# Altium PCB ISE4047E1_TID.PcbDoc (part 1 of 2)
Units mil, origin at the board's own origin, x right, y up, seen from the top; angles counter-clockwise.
Board outline 2952.76 x 1377.95 mil, 4 copper layers (Layer 1 - Top Layer, Layer 2 - GND, Layer 3 - PWR, Layer 4 - Bottom Layer), stack 43.668 mil thick; 130 components, 47 nets, 287 pads, 266 vias.
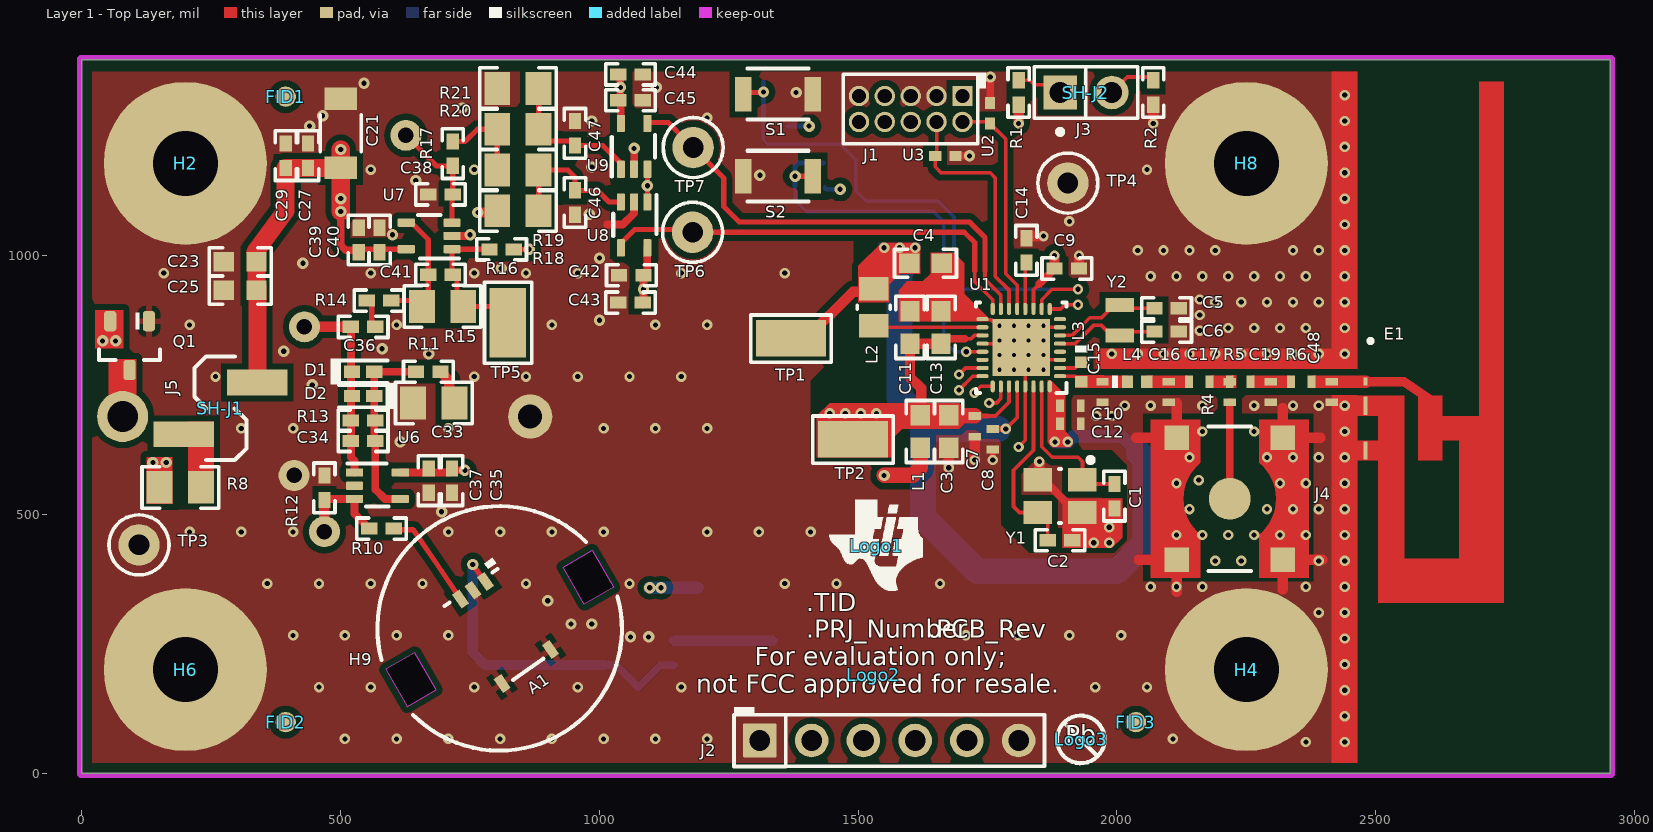
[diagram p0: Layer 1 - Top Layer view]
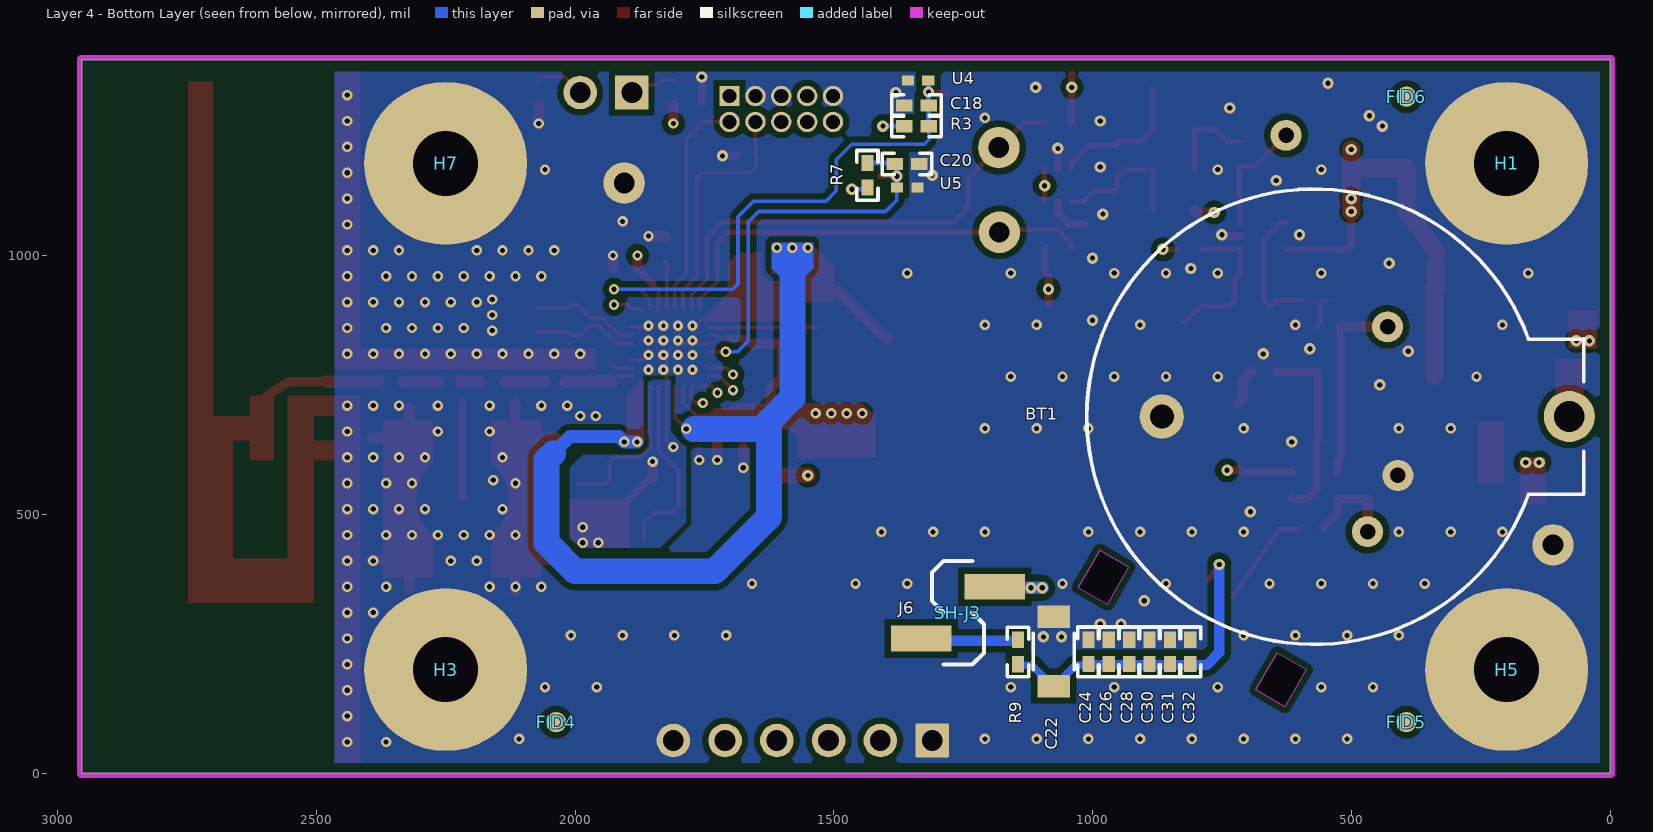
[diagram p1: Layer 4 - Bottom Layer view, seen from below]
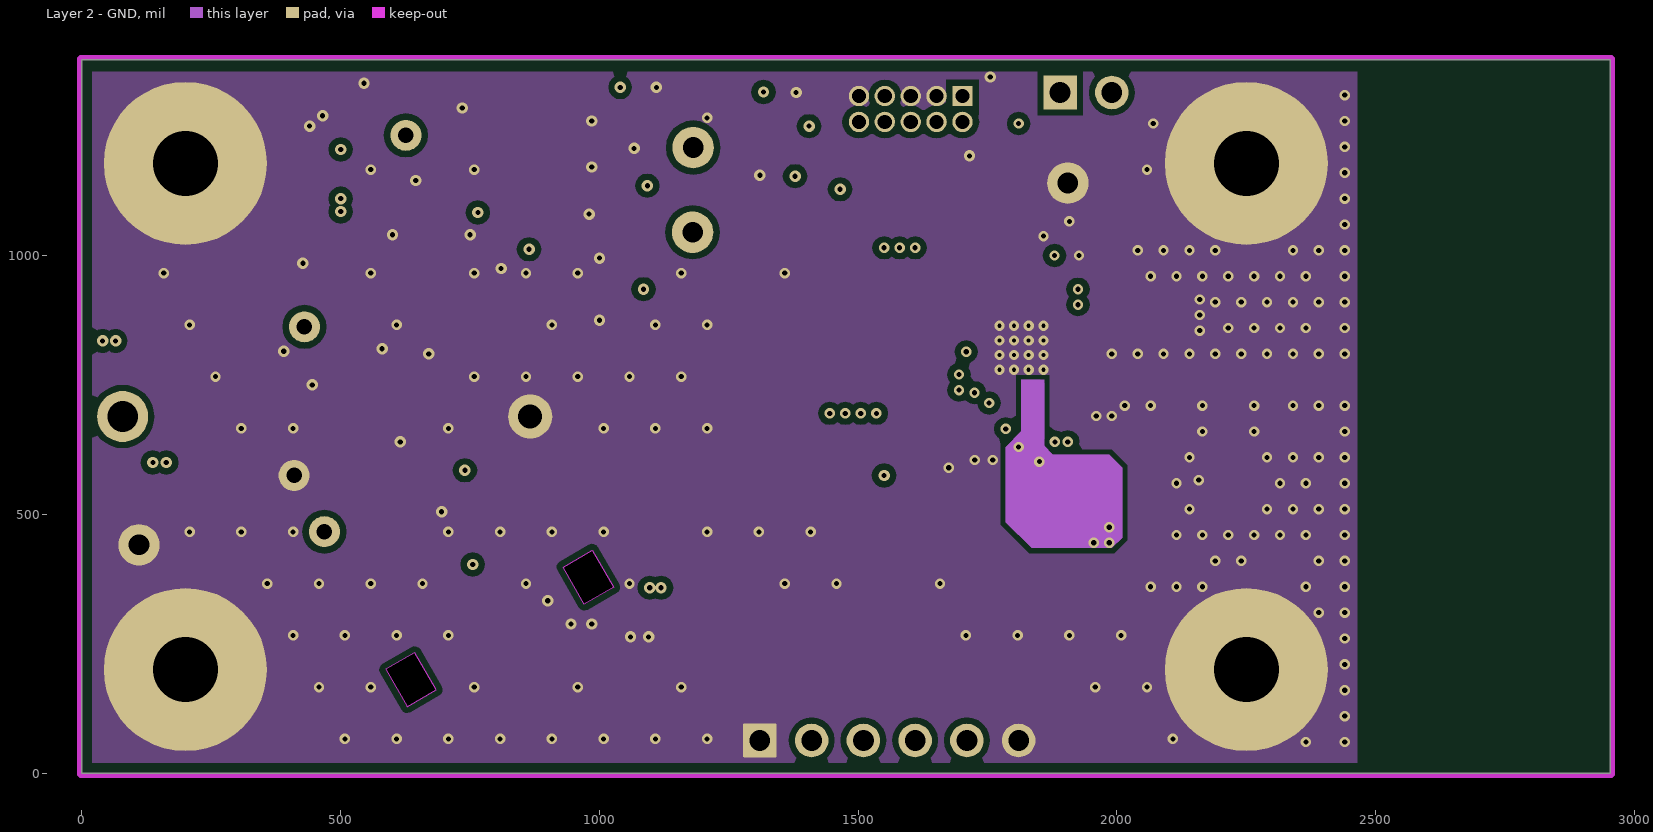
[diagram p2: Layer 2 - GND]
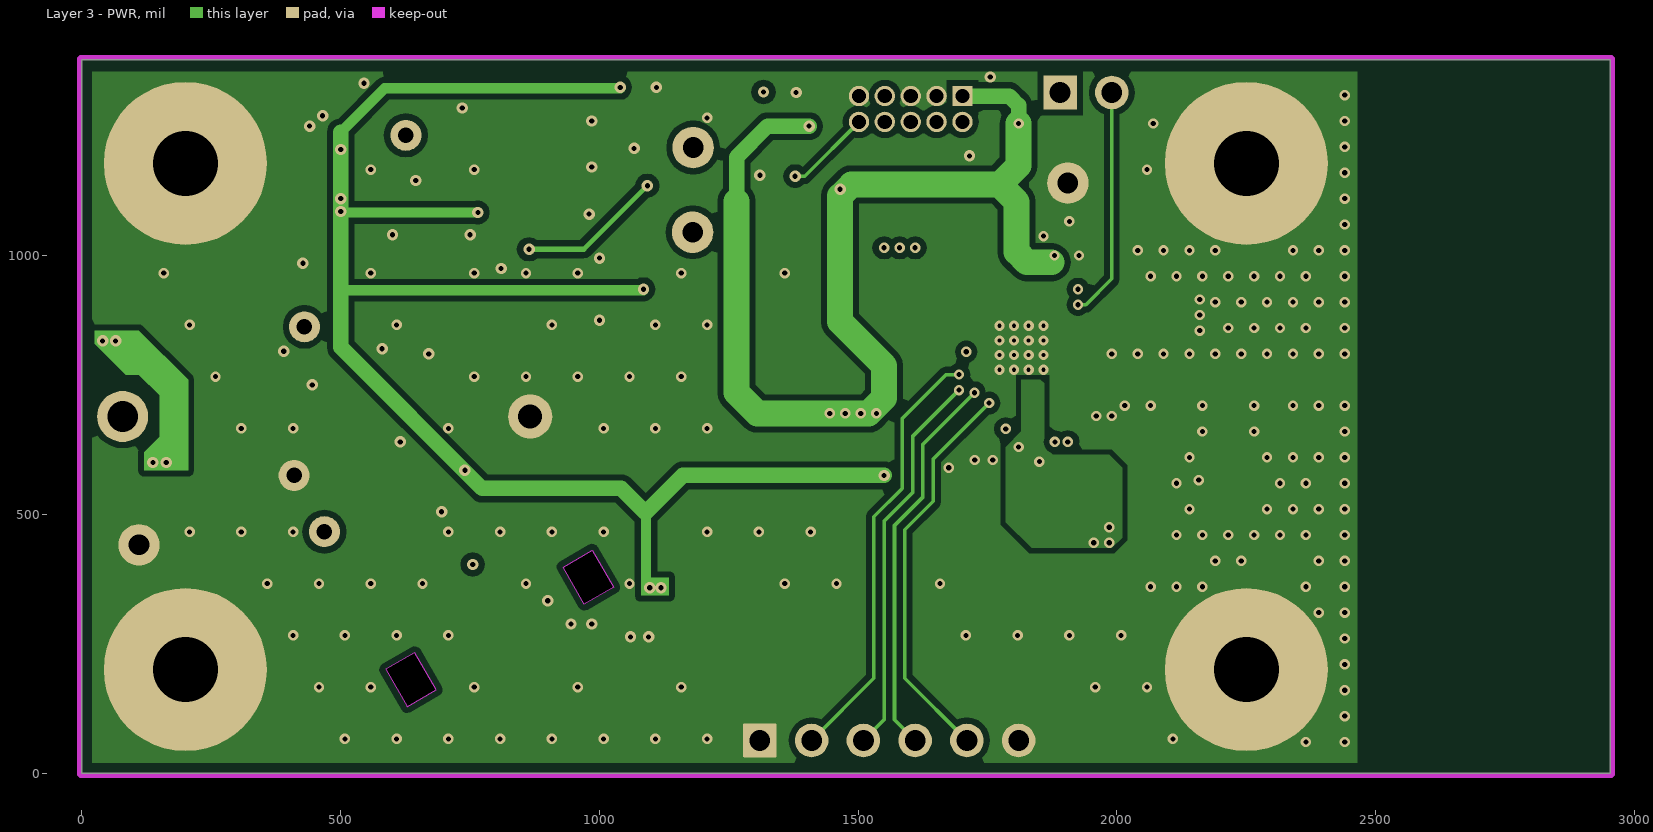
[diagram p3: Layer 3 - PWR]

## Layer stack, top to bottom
Top Solder: solder mask 0.4, Solder Resist, Dk 3.5
Layer 1 - Top Layer: signal copper 1.417
Dielectric 1: prepreg 14, 370HR, Dk 4.2
Layer 2 - GND: signal copper 1.417
Dielectric 2: core 10, 370HR, Dk 4.2
Layer 3 - PWR: signal copper 1.417
Dielectric 3: prepreg 14, 370HR, Dk 4.2
Layer 4 - Bottom Layer: signal copper 1.417
Bottom Solder: solder mask 0.4, Solder Resist, Dk 3.5

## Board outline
0,0 2952.76,0 2952.76,1377.95 0,1377.95

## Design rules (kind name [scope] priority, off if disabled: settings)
Clearance Clearance_1 [inpoly] p1: gap=12
Clearance "Stitching GND" [IsStitchingVia and InNet('GND') vs (IsVia and (Not IsStitchingVia)) Or IsPad] p2: gap=20
Clearance [All] p3: gap=6
ComponentClearance "ComponentClearance_RF Chain" [(InComponent('R4') OR InComponent('R5'))] p1: gap=0 collisioncheckmode=3 verticalgap=0 showdistances=FALSE
ComponentClearance ComponentClearance_Shunt [InComponentClass('Header') vs InComponentClass('Shunt')] p2: gap=0 collisioncheckmode=3 verticalgap=0 showdistances=FALSE
ComponentClearance ComponentClearance_H9 [incomponent('A1') vs incomponent('H9')] p3: gap=0 collisioncheckmode=3 verticalgap=0 showdistances=FALSE
ComponentClearance [All] p4: gap=3.94 collisioncheckmode=3 verticalgap=3.94 showdistances=FALSE
FabricationTestPointUsage TestPointUsage [All] p1: valid=0 allowmultiple=FALSE
FabricationTestpoint Testpoint [All] p1: side=3 testpointundercomponent=TRUE minsize=40 maxsize=100 preferedsize=60 minholesize=0 maxholesize=40 preferedholesize=32 testpointgrid=1 allowsidetop=TRUE allowsidebottom=TRUE usegrid=TRUE gridtolerance=0.01
HoleSize [All] p1: absolutevalues=TRUE maxlimit=500 minlimit=7.8 maxpercent=80.000 minpercent=20.000
MinimumSolderMaskSliver [All] p1: minsoldermaskwidth=4
PolygonConnect PolygonConnect_TR [incomponent('A1') or  incomponent('Q1') or incomponent('J4')] p1: connectstyle=Relief reliefconductorwidth=12 reliefentries=4 polygonreliefangle="90 Angle" airgapwidth=10
PolygonConnect [All] p2: connectstyle=Direct reliefconductorwidth=10 reliefentries=4 polygonreliefangle="90 Angle" airgapwidth=10
RoutingVias [All] p1: holewidth=10 width=22 viastyle="Through Hole" minholewidth=7.8 minwidth=19 maxholewidth=28 maxwidth=50
SilkToBoardRegionClearance [All] p1 off:
SilkToSilkClearance SilkToSilkClearance_1 [(HasFootprint('Pb-Free_Overlay_Medium') OR HasFootprint('Pb-Free_Overlay_Small')) vs (HasFootprint('Pb-Free_Overlay_Medium') OR HasFootprint('Pb-Free_Overlay_Small'))] p1: silktosilkclearance=0
SilkToSilkClearance [All] p2: silktosilkclearance=3
SilkToSolderMaskClearance SilkscreenOverComponentPads [IsPad] p1: minsilkscreentomaskgap=3 clearancetoexposedcopper=TRUE
SolderMaskExpansion [All] p1: expansion=1.97
UnpouredPolygon [All] p1: allowunpoured=FALSE
Width [All] p1: maxlimit=100 minlimit=6 preferedwidth=10 minimp=50.000000 maximp=50.000000 favimp=50.000000
21 further rules are at their usual default settings.

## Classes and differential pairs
component class FiducialMark: FID1 FID2 FID3 FID4 FID5 FID6
component class ISE4047E1_TID_Hardware: FID1 FID2 FID3 FID4 FID5 FID6 H1 H2 H3 H4 H5 H6 H7 H8 H9 Logo1 Logo2 Logo3 SH-J1 SH-J2 SH-J3 ZZ1 ZZ2 ZZ3 ZZ4
component class Logo: Logo1
component class "Mounting Holes": H2 H4 H6 H8
component class Header: J1 J2 J3 J5 J6
component class AssemblyNote: ZZ1 ZZ2 ZZ3 ZZ4
component class Shunt: SH-J1 SH-J2 SH-J3
component class ISE4047E1_MCU: C1 C2 C3 C4 C5 C6 C7 C8 C9 C10 C11 C12 C13 C14 C15 C16 C17 C18 C19 C20 C48 E1 J1 J2 J3 J4 L1 L2 L3 L4 R1 R2 R3 R4 R5 R6 R7 S1 S2 TP1 TP2 U1 U2 U3 U4 U5 Y1 Y2
component class ISE4047E1_POWER_PIR: A1 BT1 C21 C22 C23 C24 C25 C26 C27 C28 C29 C30 C31 C32 C33 C34 C35 C36 C37 C38 C39 C40 C41 C42 C43 C44 C45 C46 C47 D1 D2 J5 J6 Q1 R8 R9 R10 R11 R12 R13 R14 R15 R16 R17 R18 R19 R20 R21 TP3 TP4 TP5 TP6 TP7 U6 U7 U8 U9

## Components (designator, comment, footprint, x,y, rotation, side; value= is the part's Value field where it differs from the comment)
A1 "IRS-B210ST01-R1" Murata_IRS-B210ST01 807.09,279.53 r305 top locked
BT1 "BS-7" BAT_BS-7 472.44,688.98 r0 bottom locked
C1 "GRM1555C1E120JA01D" 0402 1995,535 r90 top
C2 "GRM1555C1E120JA01D" 0402 1890,450 r180 top
C3 "Used in BOM report" 0603 1675,660 r270 top
C4 "GRM188R60J106ME47D" 0603 1630,985 r180 top
C5 "GRM1555C1E120JA01D" 0402 2096,898 r0 top
C6 "GRM1555C1E120JA01D" 0402 2096,853 r0 top
C7 "GRM155R70J104KA01D" 0402S 1725,670 r270 top
C8 "GRM155R70J104KA01D" 0402S 1760,645 r270 top
C9 "GRM155R70J104KA01D" 0402 1903,975 r0 top
C10 "GRM155R70J104KA01D" 0402S 1910,710 r0 top
C11 "GRM188R60J106ME47D" 0603 1600,861 r270 top
C12 "Used in BOM report" 0402S 1910,675 r0 top
C13 "GRM188R71E104KA01D" 0603 1660,861 r270 top
C14 "GRM155R61A105KE15D" 0402 1825,1010 r90 top
C15 "GRM1555C1H1R2BA01D" 0402S 1972,736.3 r270 top
C16 "GRM1555C1H1R2BA01D" 0402S 2100,736.3 r270 top
C17 "GRM1555C1H120JA01D" 0402S 2159,756.3 r180 top
C18 "C1005X7R1H222K" 0402 1340,1290 r180 bottom
C19 "Used in BOM report" 0402S 2297,736.3 r90 top
C20 "C1005X7R1H222K" 0402 1358.37,1176.9 r0 bottom
C21 "C3216X5R1A107M160AC" 1206_190 500,1236.22 r90 top
C22 "C3216X5R1A107M160AC" 1206_190 1075,235 r90 bottom
C23 "C1608X5R0J106M" 0603 305.78,988.19 r180 top
C24 "GRM155R60J106ME44D" 0402 1007.89,234.25 r90 bottom
C25 "C1608X7R1C105K" 0603 305.78,933.07 r180 top
C26 "C1005X5R1A105K050BB" 0402 968.52,234.25 r90 bottom
C27 "C1005X7R1H104K050BB" 0402 437.01,1192.91 r90 top
C28 "C1005X7R1H104K050BB" 0402 929.15,234.25 r90 bottom
C29 "C1005X7R1C103K050BA" 0402 393.7,1192.91 r90 top
C30 "C1005X7R1C103K050BA" 0402 889.78,234.25 r90 bottom
C31 "C1005X7R1H102K" 0402 850.41,234.25 r90 bottom
C32 "C0402C101J3GACTU" 0402 811.04,234.25 r90 bottom
C33 "C2012X5R1A336M125AC" 0805_HV 680,715 r180 top
C34 "C1005X7R1E103K" 0402 543.31,641.73 r0 top
C35 "C1005X7R1H104K" 0402 715,565 r90 top
C36 "C1005X5R1A335K050BC" 0402 543.31,862.2 r180 top
C37 "C1005X7R1H102K" 0402 670,565 r270 top
C38 "C1005X7R1H104K" 0402 692.91,1118.11 r180 top
C39 "C1005X7R1H104K" 0402 535,1030 r270 top
C40 "C1005X7R1H102K" 0402 575,1030 r90 top
C41 "C1005C0G1E102J" 0402 693,963 r180 top
C42 "C1005X7R1H104K" 0402 1061.54,962.03 r0 top
C43 "C1005X7R1H102K" 0402 1060,909 r180 top
C44 "C1005X7R1H104K" 0402 1060,1350 r180 top
C45 "C1005X7R1H102K" 0402 1060,1300 r0 top
C46 "C1005X7R1H104K" 0402 952.76,1102.36 r270 top
C47 "C1005X7R1H104K" 0402 952.76,1236.22 r90 top
C48 "Used in BOM report" 0402S 2415,736.3 r90 top
D1 "1N4148X-TP" SOD-523 543.31,775.59 r0 top
D2 "1N4148X-TP" SOD-523 543.31,728.35 r180 top
E1 "ANTENNA_DN007A" ANTENNA_DN007A 2480.32,756.03 r270 top locked net-tie
FID1 "Fiducial" Fiducial10-20 393.7,1307.09 r0 top
FID2 "Fiducial" Fiducial10-20 393.7,98.42 r0 top
FID3 "Fiducial" Fiducial10-20 2036.61,98.42 r0 top
FID4 "Fiducial" Fiducial10-20 2036.61,98.42 r90 bottom
FID5 "Fiducial" Fiducial10-20 393.7,98.42 r90 bottom
FID6 "Fiducial" Fiducial10-20 393.7,1307.09 r90 bottom
H1 "1902C" Keystone_1902C#1 200,1177.95 r180 bottom
H2 "NY PMS 440 0025 PH" "NY PMS 440 0025 PH" 200,1177.95 r0 top
H3 "1902C" Keystone_1902C#2 2250,200 r180 bottom locked
H4 "NY PMS 440 0025 PH" "NY PMS 440 0025 PH" 2250,200 r0 top locked
H5 "1902C" Keystone_1902C#2 200,200 r180 bottom locked
H6 "NY PMS 440 0025 PH" "NY PMS 440 0025 PH" 200,200 r0 top locked
H7 "1902C" Keystone_1902C#1 2250,1177.95 r180 bottom
H8 "NY PMS 440 0025 PH" "NY PMS 440 0025 PH" 2250,1177.95 r0 top
H9 "IML-0669" Murata_IML-0669 807.09,279.53 r210 top locked
J1 "GRPB052VWVN-RC" CONN_GRPB052VWVN-RC 1601.42,1283.19 r180 top
J2 "TSW-106-07-G-S" TSW-106-07-G-S 1560,62.99 r0 top
J3 "TSW-102-07-G-S" TSW-102-07-G-S 1940,1315 r0 top
J4 "CONSMA001-SMD-G" Linx_CONSMA001-SMD-G 2218,530 r0 top
J5 "87898-0204" Molex_87898-0204 267.72,704.72 r90 top
J6 "87898-0204" Molex_87898-0204 1260,310 r90 bottom
L1 "BLM18HE152SN1D" 0603 1620,660 r90 top
L2 "CKS2125100M-T" 0805_145 1530,900 r90 top
L3 "LQG15HS15NJ02D" IND_LQG15H#1 1931,775 r270 top
L4 "LQG15HS2N0S02D" IND_LQG15H#2 2039,756.3 r0 top
Logo1 "Texas Instruments" TI_Symbol_Overlay_Small 1534.51,439.64 r0 top
Logo2 "FCC disclaimer" FCC_disclaimer_stacked 1529.51,189.64 r0 top
Logo3 "Pb-Free Symbol" Pb-Free_Overlay_Small 1930,65 r0 top
Q1 "SI2323DS" SOT-23 92,826 r270 top
R1 "CRCW04020000Z0ED" 0402 1810,1315 r270 top
R2 "CRCW0402100KFKED" 0402 2070,1315 r90 top
R3 "CRCW040247K5FKED" 0402 1340,1250 r0 bottom
R4 "CRCW04020000Z0ED" 0402S 2218,736.3 r270 top
R5 "CRCW04020000Z0ED" 0402S 2238,756.3 r0 top
R6 "CRCW04020000Z0ED" 0402S 2356,756.3 r0 top
R7 "CRCW040247K5FKED" 0402 1435,1155 r270 bottom
R8 "CRCW08050000Z0EA" 0805_HV 190,552 r0 top
R9 "CRCW0402619KFKED" 0402 1144,234 r90 bottom
R10 "CRCW04020000Z0ED" 0402 578.74,472.44 r180 top
R11 "CRCW04026K81FKED" 0402 669.29,775.59 r180 top
R12 "CRCW04021M30FKED" 0402 468.5,551.18 r270 top
R13 "CRCW04021M50FKED" 0402 543.31,681.1 r180 top
R14 "CRCW040268K1FKED" 0402 574,913 r0 top
R15 "RMCF0805JT15M0" 0805_HV 696.85,901.57 r0 top
R16 "CRCW04020000Z0ED" 0402 811.02,1011.81 r0 top
R17 "CRCW04020000Z0ED" 0402 716.54,1196.85 r90 top
R18 "RMCF0805JT15M0" 0805_HV 842.52,1086.61 r180 top
R19 "RMCF0805JT15M0" 0805_HV 842.52,1165.35 r0 top
R20 "RMCF0805JT15M0" 0805_HV 842.52,1244.09 r180 top
R21 "RMCF0805JT15M0" 0805_HV 842.52,1322.84 r0 top
S1 "B3U-1000P" SW_B3U-1000P 1345,1312 r180 top
S2 "B3U-1000P" SW_B3U-1000P 1345,1153.26 r0 top
SH-J1 "969102-0000-DA" SNT-100-BK-G#1 267.72,704.72 r270 top
SH-J2 "969102-0000-DA" SNT-100-BK-G#1 1940,1315 r0 top
SH-J3 "969102-0000-DA" SNT-100-BK-G#2 1260,310 r270 bottom
TP1 "5015" Testpoint_Keystone_Miniature 1370,840 r0 top
TP2 "5015" Testpoint_Keystone_Miniature 1490,645 r0 top
TP3 "5001" Keystone5001 110.24,440.94 r0 top
TP4 "5001" Keystone5001 1905,1140 r0 top
TP5 "5015" Testpoint_Keystone_Miniature 822.84,870.08 r90 top
TP6 "5004" Keystone5004 1180,1045 r0 top
TP7 "5004" Keystone5004 1181.1,1208.66 r0 top
U1 "CC2650F128RSMR" RSM0032B 1815,822 r180 top locked
U2 "TPD1E10B06DPYR" DPY0002A 1754.69,1275.04 r90 top
U3 "TPD1E10B06DPYR" DPY0002A 1668.35,1192.64 r0 top
U4 "TPD1E10B06DPYR" DPY0002A 1337,1338 r0 bottom
U5 "TPD1E10B06DPYR" DPY0002A 1358.09,1131.3 r180 bottom
U6 "LPV521MG" DCK0005A_N 570.87,555.12 r0 top
U7 "LPV521MG" DCK0005A_N 670.9,1037.87 r180 top
U8 "TLV3691IDCKR" DCK0005A_N 1066.93,1059.05 r270 top
U9 "TLV3691IDCKR" DCK0005A_N 1067,1211 r90 top
Y1 "TSX-3225 24.0000MF20G-AC3" EPSON_TSX-3225 1890,535 r270 top
Y2 "FC-12M 32.7680KA-A3" Epson_FC-12M 2005,875 r90 top
ZZ1 "These assemblies are ESD sensitive, ESD precautions shall be observed." AssemblyNote 160,1950 r0 top
ZZ2 "These assemblies must be clean and free from flux and all contaminants. Use of no clean flux is not acceptable." AssemblyNote 160,1820 r0 top
ZZ3 "These assemblies must comply with workmanship standards IPC-A-610 Class 2, unless otherwise specified." AssemblyNote 160,1695 r0 top
ZZ4 "After verifying lens of A1 is clean and undistorted, snap cover H9 over sensor A1 during final hardware assembly." AssemblyNote 160,1575 r0 top

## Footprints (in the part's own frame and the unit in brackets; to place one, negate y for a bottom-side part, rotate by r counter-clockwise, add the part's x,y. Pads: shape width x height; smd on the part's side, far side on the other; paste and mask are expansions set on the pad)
0402 [mm] "0402 from SM-752 data"
  rect 0.8x0.6 smd: 1(-0.6,0) 2(0.6,0)
  silkscreen extent -1.22,-0.52 1.22,0.52, body extent -0.55,-0.3 0.55,0.3, height 0.6
0402S [mil] "Based on C0402S footprint from PADS legacy"
  rect 15x24 smd: 1(-20,0) 2(20,0)
  body extent -22,-12 22,12, height 24
0603 [mm] "0603 from SM-752 data"
  rect 1x0.95 smd: 1(-0.8,0) 2(0.8,0)
  silkscreen extent -1.52,-0.69 1.52,0.69, body extent -0.87,-0.47 0.87,0.47, height 1
0805_145 [mm] "0805 / 1.45mm height"
  rect 1.15x1.45 smd: 1(-0.9,0) 2(0.9,0)
  silkscreen extent -0.1,-0.8 0.1,0.8, body extent -1.1,-0.72 1.1,0.72, height 1.45
0805_HV [mil] "0805 with 30mil clearance between pads"
  rect 50x63 smd: 1(-40,0) 2(40,0)
  silkscreen extent -74,-40 74,40, body extent -43,-29 43,29, height 57
1206_190 [mm] "1206_190"
  rect 1.1x1.6 smd: 1(-1.7,0) 2(1.7,0)
  silkscreen extent -0.9,-1 0.9,1, body extent -1.75,-0.95 1.75,0.95, height 1.9
ANTENNA_DN007A [mm] "SMD, 3-Leads"
  rect 0.4x0.2 smd paste-2 mask-2: 1(-0.007,0)
  rect 0.9x0.2 smd paste-2 mask-2: 2(1.18,-0.01) 3(3.37,0)
  Layer 1 - Top Layer region: 10.84,0.63 10.84,6.775 -14.715,6.775 -14.715,5.59 1.685,5.59 1.685,3.765 0.685,3.765 0.685,3.271 -0.225,1.951 -0.225,-0.11 0.21,-0.11 0.21,1.816 0.737,2.58 3.86,2.58 3.86,3.765 2.86,3.765 2.86,4.59 8.685,4.59 8.685,1.895 0.685,1.895 0.685,-0.11 1.66,-0.11 1.66,0.63 2.885,0.63 2.885,-0.11 3.86,-0.11 3.86,0.63
  silkscreen extent -2.11,0.15 -1.91,0.35
AssemblyNote [mil] "Assembly Note"
BAT_BS-7 [mm] "Memory Protection Devices CR2032 battery holder"
  round 2.5 hole 1.5: 1(-10,0)
  round 2.17 hole 1.181: 2(10,0)
  silkscreen extent -10.7,-11.16 13.68,11.18, body extent -10.69,-11.16 13.7,11.16, height 9.02
CONN_GRPB052VWVN-RC [mm] "SULLINS"
  rect 1x1 hole 0.7 mask+0.08: 1(-2.54,-0.635)
  round 1 hole 0.7 mask+0.08: 2(-2.54,0.635) 3(-1.27,-0.635) 4(-1.27,0.635) 5(0,-0.635) 6(0,0.635) 7(1.27,-0.635) 8(1.27,0.635) 9(2.54,-0.635) 10(2.54,0.635)
  silkscreen extent -3.7,-1.8 3.3,1.7, body extent -3.17,-1.7 3.17,1.7, height 4
DCK0005A_N [mm] "SOT353, 5-Leads, Body 2x1.3mm, Pitch 0.65mm, Lead Span 2.1mm, IPC Medium Density"
  rrect25% 0.85x0.4 smd: 1(-1.125,0.65) 2(-1.125,0) 3(-1.125,-0.65) 4(1.125,-0.65) 5(1.125,0.65)
  silkscreen extent -1.48,-1.02 0.55,1.1, body extent -1.14,-1 1.14,1, height 0.95
DPY0002A [mm] "R-PX2SON-N2"
  rect 0.6x0.5 smd: 1(-0.5,0) 2(0.5,0)
  body extent -0.55,-0.35 0.55,0.35, height 0.4
Epson_FC-12M [mm] "Epson"
  rect 0.7x1.4 smd: 1(-0.75,0) 2(0.75,0)
  body extent -1.05,-0.63 1.05,0.63, height 0.6
EPSON_TSX-3225 [mm] "SMD, 4-Leads, Body 2.65x3.35mm, Height 0.6mm"
  rect 1.15x1.4 smd: 1(-0.8,1.1) 2(-0.8,-1.1) 3(0.8,-1.1) 4(0.8,1.1)
  silkscreen extent -1.9,-0.05 1.33,1.63, body extent -1.33,-1.68 1.33,1.68, height 0.61
FCC_disclaimer_stacked [mil]
Fiducial10-20 [mm]
  round 1 smd mask+0.5: 1(0,0)
IND_LQG15H#1 [mm] "MuRata"
  rect 0.55x0.6 smd: 1(-0.475,0) 2(0.475,0)
  silkscreen extent -1.3,-0.3 -0.95,0.3, body extent -0.52,-0.27 0.52,0.27, height 0.55
IND_LQG15H#2 [mm] "MuRata"
  rect 0.55x0.61 smd: 1(-0.475,0) 2(0.475,0)
  silkscreen extent -1.23,-0.3 -0.95,0.3, body extent -0.52,-0.27 0.52,0.27, height 0.55
Keystone5001 [mil] "For Keystone 500x miniature loop terminals"
  round 80 hole 40: 1(0,0)
  silkscreen extent -58,-58 58,58, body extent -49,-49 49,49, height 182
Keystone5004 [mil] "For Keystone 500x miniature loop terminals"
  round 80 hole 40: 1(0,0)
  silkscreen extent -58,-58 58,58, body extent -49,-49 49,49, height 182
Keystone_1902C#1 [mil] "Hex Standoff, 4-40 threaded, nylon"
  round 1 on Mech4: 0(0,0)
  body extent -145,-126 146,126, height 501
Keystone_1902C#2 [mil] "Hex Standoff, 4-40 threaded, nylon"
  body extent -145,-126 146,126, height 501
Linx_CONSMA001-SMD-G [mm] "SMD, 5-Leads, Body 7x7mm, Height 10.5mm"
  round 2.05 smd: 1(0,0)
  rect 1.2x1.2 smd: 2(-2.6,-3) 3(2.6,-3) 4(2.6,3) 5(-2.6,3)
  Layer 1 - Top Layer region: -3.88,-3.88 -1.44,-3.88 -1.44,-1.761 -1.448,-1.761 -2.062,-0.974 -2.28,0 -2.062,0.974 -1.448,1.761 -1.448,1.761 -1.44,1.761 -1.44,3.88 -3.88,3.88
  Layer 1 - Top Layer region: 3.88,-3.88 1.44,-3.88 1.44,-1.761 1.448,-1.761 2.062,-0.974 2.28,0 2.062,0.974 1.448,1.761 1.448,1.761 1.44,1.761 1.44,3.88 3.88,3.88
  silkscreen extent -1.04,-3.55 1.04,3.55, body extent -3.55,-3.55 3.55,3.55, height 10.5
Molex_87898-0204 [mm] "Header, 2.54 mm, 2x1, R/A, SMT"
  rect 1.27x2.96 smd: 1(-1.27,1.8) 2(1.27,-1.8)
  silkscreen extent -2.54,-1.27 2.54,1.27, body extent -2.54,-2.4 2.54,2.4, height 9.65
Murata_IML-0669 [mil] "Pyroelectric Infrared Lens, TH"
  Keep-Out Layer board cut-out: -165.35,-41.34 -230.31,-41.34 -230.31,41.34 -165.35,41.34
  Keep-Out Layer board cut-out: 165.35,-41.34 230.31,-41.34 230.31,41.34 165.35,41.34
  silkscreen extent -228,-236 228,236, body extent -256,-236 256,236, height 335
Murata_IRS-B210ST01 [mm] "SMD, 5-Leads, Body 4.7x4.7mm"
  rect 0.825x0.45 smd: 1(-2.288,0.75) 2(-2.288,0) 3(-2.288,-0.75) 4(2.288,-1.45) 5(2.288,1.45)
  silkscreen extent -3.05,-1.6 2.45,1.7, body extent -2.45,-2.45 2.45,2.45, height 2.61
"NY PMS 440 0025 PH" [mm] "4-40 nylon screw and mounting hole"
  round 8 hole 3.2: 1(0,0)
  body extent -3.3,-3.3 3.3,3.3, height 2.69
Pb-Free_Overlay_Small [mil]
  silkscreen extent -46,-46 46,46
RSM0032B [mm] "QFN, 32-Leads, Body 4x4mm, Pitch 0.4mm, Thermal Pad 2.8x2.8mm, TI Recommended"
  oval 0.6x0.2 smd mask+0.025: 1(-1.9,1.4) 2(-1.9,1) 3(-1.9,0.6) 4(-1.9,0.2) 5(-1.9,-0.2) 6(-1.9,-0.6) 7(-1.9,-1) 8(-1.9,-1.4) 17(1.9,-1.4) 18(1.9,-1) 19(1.9,-0.6) 20(1.9,-0.2) 21(1.9,0.2) 22(1.9,0.6) 23(1.9,1) 24(1.9,1.4)
  oval 0.2x0.6 smd mask+0.025: 9(-1.4,-1.9) 10(-1,-1.9) 11(-0.6,-1.9) 12(-0.2,-1.9) 13(0.2,-1.9) 14(0.6,-1.9) 15(1,-1.9) 16(1.4,-1.9) 25(1.4,1.9) 26(1,1.9) 27(0.6,1.9) 28(0.2,1.9) 29(-0.2,1.9) 30(-0.6,1.9) 31(-1,1.9) 32(-1.4,1.9)
  rect 2.8x2.8 smd paste-1.4 mask+0.025: 33(0,0)
  silkscreen extent -2.23,-2.23 2.23,2.23, body extent -2.07,-2.07 2.08,2.08, height 1.01
SNT-100-BK-G#1 [mil] "Samtec STEP model"
  round 1 on Mech3: 0(0,0)
  body extent -100,-50 100,50, height 344
SNT-100-BK-G#2 [mil] "Samtec STEP model"
  round 1 on Mech4: 0(0,0)
  body extent -100,-50 100,50, height 344
SOD-523 [mm] "NXP Semiconductor recommended land pattern, nominal STEP model"
  rect 0.8x0.6 smd paste-0.05: 1(-0.55,0) 2(0.55,0)
  silkscreen extent -1.6,-0.64 1.2,0.64, body extent -0.8,-0.4 0.8,0.4, height 0.72
SOT-23 [mm] "SOT23, 3-Leads, Body 2.9x1.3mm, Pitch 0.95mm, Lead Span 2.5mm, IPC Medium Density"
  rrect50% 1x0.6 smd: 1(-1.2,0.95) 2(-1.2,-0.95) 3(1.2,0)
  silkscreen extent -1.63,-1.5 0.7,1.5, body extent -1.16,-1.45 1.21,1.45, height 1
SW_B3U-1000P [mm] "OMRON"
  rect 0.8x1.7 smd: 1(-1.7,0) 2(1.7,0)
  silkscreen extent -1.5,-1.25 1.5,1.25, body extent -1.5,-1.25 1.5,1.25, height 1.75
Testpoint_Keystone_Miniature [mil] "Miniature SMT test point"
  rect 135x70 smd: 1(0,0)
  silkscreen extent -78,-46 78,45, body extent -52,-20 52,20, height 61
TI_Symbol_Overlay_Small [mil]
  silkscreen extent -90,-88 91,88
TSW-102-07-G-S [mm] "Samtec 100mil, 1x2, 230 mil above insulator"
  rect 1.65x1.65 hole 1.016 mask+0: 1(-1.27,0)
  round 1.65 hole 1.016 mask+0: 2(1.27,0)
  silkscreen extent -2.54,-2.06 2.54,1.27, body extent -2.54,-1.27 2.54,1.27, height 8.38
TSW-106-07-G-S [mm] "Samtec 100mil, 1x6, 230 mil above insulator"
  rrect6% 1.65x1.65 hole 1.016: 1(-6.35,0)
  round 1.65 hole 1.016: 2(-3.81,0) 3(-1.27,0) 4(1.27,0) 5(3.81,0) 6(6.35,0)
  silkscreen extent -7.62,-1.27 7.62,1.65, body extent -7.62,-1.27 7.62,1.27, height 8.38

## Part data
A1: "Pyroelectric Infrared Sensors for Reflow Soldering, 3.6mVp-p, SMD"
BT1: "Battery Holder, CR2032, Retainer clip, TH"
C1 C2 C5 C6: "CAP, CERM, 12 pF, 25 V, +/- 5%, C0G/NP0, 0402"
C3 C12 C19 C48: library part Capacitor, "CAP, CERM, xxxF, xxV, [TempCo], xx%, [PackageReference]"
C4 C11 C23: "CAP, CERM, 10 µF, 6.3 V, +/- 20%, X5R, 0603"
C7 C8 C9 C10: "CAP, CERM, 0.1 µF, 6.3 V, +/- 10%, X7R, 0402"
C13: "CAP, CERM, 0.1 µF, 25 V, +/- 10%, X7R, 0603"
C14 C26: "CAP, CERM, 1 µF, 10 V, +/- 10%, X5R, 0402"
C15 C16: "CAP, CERM, 1.2 pF, 50 V, +/- 8.3%, C0G/NP0, 0402"
C17: "CAP, CERM, 12 pF, 50 V, +/- 5%, C0G/NP0, 0402"
C18 C20: "CAP, CERM, 2200 pF, 50 V, +/- 10%, X7R, 0402"
C21 C22: "CAP, CERM, 100 µF, 10 V, +/- 20%, X5R, 1206_190"
C24: "CAP, CERM, 10 µF, 6.3 V, +/- 20%, X5R, 0402"
C25: "CAP, CERM, 1 µF, 16 V, +/- 10%, X7R, 0603"
C27 C28 C35 C38 C39 C42 C44 C46 C47: "CAP, CERM, 0.1 µF, 50 V, +/- 10%, X7R, 0402"
C29 C30: "CAP, CERM, 0.01 µF, 16 V, +/- 10%, X7R, 0402"
C31 C37 C40 C43 C45: "CAP, CERM, 1000 pF, 50 V, +/- 10%, X7R, 0402"
C32: "CAP, CERM, 100 pF, 25 V, +/- 5%, C0G/NP0, 0402"
C33: "CAP, CERM, 33 µF, 10 V, +/- 20%, X5R, 0805"
C34: "CAP, CERM, 0.01 µF, 25 V, +/- 10%, X7R, 0402"
C36: "CAP, CERM, 3.3 µF, 10 V, +/- 10%, X5R, 0402"
C41: "CAP, CERM, 1000 pF, 25 V, +/- 5%, C0G/NP0, 0402"
D1 D2: "Diode, Switching, 75 V, 0.3 A, SOD-523"
E1: "2.4GHz PCB Antenna.  There is nothing to buy or mount."
FID1 FID2 FID3 FID4 FID5 FID6: "Fiducial mark.  There is nothing to buy or mount."
H1 H3 H5 H7: "Standoff, Hex, 0.5\"L #4-40 Nylon"
H2 H4 H6 H8: "Machine Screw, Round, #4-40 x 1/4, Nylon, Philips panhead"
H9: "Lens, Ceiling Mount, TH"
J1: "Header, 50mil, 5x2, Gold, TH"
J2: "Header, 100mil, 6x1, Gold, TH"
J3: "Header, 100mil, 2x1, Gold, TH"
J4: "Jack, SMA, PCB, Gold, SMT"
J5 J6: "Header, 2.54 mm, 2x1, Gold, R/A, SMT"
L1: "Ferrite Bead, 1500 ohm @ 100 MHz, 0.5 A, 0603"
L2: "Inductor, Multilayer, Ferrite, 10uH, 0.11A, 0.52 ohm, SMD"
L3: "Inductor, Multilayer, Air Core, 15 nH, 0.3 A, 0.32 ohm, SMD"
L4: "Inductor, Multilayer, Air Core, 2 nH, 0.3 A, 0.1 ohm, SMD"
Logo1: library part TI_Logo, "Texas Instrument Corporate Signature"
Logo2: library part FCC_disclaimer, "FCC_disclaimer"
Logo3: library part Pb-Free
Q1: "MOSFET, P-CH, -20 V, -3.7 A, SOT-23"
R1 R4 R5 R6 R10 R16 R17: "RES, 0, 5%, 0.063 W, 0402"
R2: "RES, 100 k, 1%, 0.063 W, 0402"
R3 R7: "RES, 47.5 k, 1%, 0.063 W, 0402"
R8: "RES, 0, 5%, 0.125 W, 0805"
R9: "RES, 619 k, 1%, 0.063 W, 0402"
R11: "RES, 6.81 k, 1%, 0.063 W, 0402"
R12: "RES, 1.30 M, 1%, 0.063 W, 0402"
R13: "RES, 1.50 M, 1%, 0.063 W, 0402"
R14: "RES, 68.1 k, 1%, 0.063 W, 0402"
R15 R18 R19 R20 R21: "RES, 15 M, 5%, 0.125 W, AEC-Q200 Grade 0, 0805"
S1 S2: "SWITCH TACTILE SPST-NO 0.05A 12V"
SH-J1 SH-J2 SH-J3: "Shunt, 100mil, Gold plated, Black"
TP1 TP2 TP5: "Test Point, Miniature, SMT"
TP3 TP4: "Test Point, Miniature, Black, TH"
TP6 TP7: "Test Point, Miniature, Yellow, TH"
U1: "Ultra low-power ARM Cortex M3 2.4 GHz Radio MCU, RSM0032B"
U2 U3 U4 U5: "ESD in 0402 Package with 10 pF Capacitance and 6 V Breakdown, 1 Channel, -40 to +125 degC, 2-pin X2SON (DPY), Green (RoHS & no Sb/Br)"
U6 U7: "Nanopower 400nA, 1.8V, R-R I/O CMOS Op Amp, DCK0005A"
U8 U9: "0.9-V to 6.5-V, Nanopower Comparator, DCK0005A"
Y1: "Crystal, 24 MHz, 9 pF, SMD"
Y2: "Crystal, 32.768kHz, 12.5pF, SMD"
ZZ1 ZZ2 ZZ3 ZZ4: library part AssemblyNote

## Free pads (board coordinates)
  round 60 hole 30: 0(410,575) 0(430,862.2) 0(468.5,466.39) 0(625.98,1232.28)

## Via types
v1: diameter 20, hole 10, Layer 1 - Top Layer to Layer 4 - Bottom Layer, tented both sides, 198 vias
v2: diameter 22, hole 10, Layer 1 - Top Layer to Layer 4 - Bottom Layer, tented both sides, 52 vias
v3: diameter 19.68, hole 7.87, Layer 1 - Top Layer to Layer 4 - Bottom Layer, tented both sides, 16 vias

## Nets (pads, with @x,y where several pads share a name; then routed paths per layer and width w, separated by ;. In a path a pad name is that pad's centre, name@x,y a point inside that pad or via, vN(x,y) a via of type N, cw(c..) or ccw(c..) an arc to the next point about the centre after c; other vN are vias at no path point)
DCDC_SW: L2.1 U1.18 | length 207
  Layer 1 - Top Layer w7: L2.1@1533.26,861.31 1740.2,861.31 U1.18@1740.2,861.37
GND: A1.2 A1.4 A1.5 BT1.2 C1.1 C2.1 C3.2 C4.1 C5.2 C6.2 C7.2 C8.2 C9.2 C10.2 C11.1 C12.2 C13.1 C14.2 C15.2 C16.2 C18.1 C19.1 C20.1 C21.2 C22.2 C23.2 C24.2 C25.2 C26.2 C27.2 C28.2 C29.2 C30.2 C31.2 C32.2 C33.2 C35.1 C37.2 C38.2 C39.1 C40.2 C42.1 C43.2 C44.1 C45.2 C46.2 C47.2 C48.1 E1.2 E1.3 H2.1 H4.1 H6.1 H8.1 J1.3 J1.5 J1.9 J2.1 J2.6 J4.2 J4.3 J4.4 J4.5 pad.0@410,575 Q1.1 R2.1 R12.1 R21.1 S1.1 S2.1 TP3.1 TP4.1 U1.3 U1.7 U1.17 U1.20 U1.29 U1.33 U2.2 U3.2 U4.2 U5.2 U6.2 U7.2 U8.2 U9.2 Y1.2 Y1.4 | length 1403.9
  Layer 1 - Top Layer w7: U1.20@1740.2,829.87 U1.33@1807.13,829.87 ; v1(1810,630) 1822.87,642.87 U1.29@1822.87,747.2 1822.87,814.13 U1.33@1815,822 ; U1.33@1863.38,798.38 U1.3@1889.8,798.38 ; U1.33@1866.37,861.37 U1.7@1889.8,861.37
  Layer 1 - Top Layer w12: v1(1760,605) C8.2@1760,625
  Layer 1 - Top Layer w15: U7.2@715.19,1037.87 747.87,1037.87 v2(750,1040) ; 1015,1060 1045,1060 1066.93,1081.93 U8.2@1066.93,1103.35 ; U9.2@1067,1166.71 v2(1067,1207) ; U3.2@1688.03,1192.64 v2(1715,1192.64) ; U2.2@1754.69,1294.72 1755,1295.03 v2(1755,1345) ; Y1.2@1856.81,568.19 Y1.4@1915,510
  Layer 1 - Top Layer w20: v1(1675,590) C3.2@1675,628.5 ; v1(1725,605) C7.2@1725,646.38 ; C14.2@1825,1037.56 v1(1858,1037.56) ; Y1.2@1850,570 v1(1850,601.81) ; C9.2@1926.62,975 v1(1926.62,1000) ; 2036.89,648.11 J4.5@2115.64,648.11 2115.64,714.36 ; 2041.89,411.89 J4.2@2115.64,411.89 v1@2115.64,350.64 ; v1(2070,1255) R2.1@2070,1291.38 ; 2320.36,355.36 J4.3@2320.36,411.89 v1@2396.89,411.89 ; 2320.36,704.64 J4.4@2320.36,648.11 2393.11,648.11
  other v1: 2365,60 2440,60 508,66 608,66 708,66 808,66 908,66 1008,66 1108,66 1208,66 2108,66 2440,110 2440,160 458,166 558,166 758,166 958,166 1158,166 1958,166 2058,166 2440,210 2440,260 408,266 508,266 608,266 708,266 1708,266 1808,266 1908,266 2008,266 2390,310 2440,310 2065,360 2115,360 2165,360 2365,360 2440,360 358,366 458,366 558,366 658,366 858,366 1058,366 1358,366 1458,366 1658,366 2190,410 2240,410 2390,410 2440,410 1955,445 1985,445 2115,460 2165,460 2215,460 2265,460 2315,460 2365,460 2440,460 208,466 308,466 408,466 708,466 808,466 908,466 1008,466 1208,466 1308,466 1408,466 1985,475 2140,510 2290,510 2340,510 2390,510 2440,510 2115,560 2315,560 2365,560 2440,560 2158,566 2140,610 2290,610 2340,610 2390,610 2440,610 2165,660 2265,660 2440,660 308,666 408,666 708,666 1008,666 1108,666 1208,666 1960,690 1990,690 2015,710 2065,710 2165,710 2265,710 2340,710 2390,710 2440,710 258,766 758,766 858,766 958,766 1058,766 1158,766 1990,810 2040,810 2090,810 2140,810 2190,810 2240,810 2290,810 2340,810 2390,810 2440,810 2160,855 2215,860 2265,860 2315,860 2365,860 2440,860 208,866 608,866 908,866 1108,866 1208,866 2160,885 2190,910 2240,910 2290,910 2340,910 2390,910 2440,910 2160,915 2065,960 2115,960 2165,960 2215,960 2265,960 2315,960 2365,960 2440,960 158,966 558,966 758,966 858,966 958,966 1158,966 1358,966 2040,1010 2090,1010 2140,1010 2190,1010 2340,1010 2390,1010 2440,1010 2440,1060 1908,1066 2440,1110 2440,1160 558,1166 758,1166 2058,1166 2440,1210 2440,1260 1208,1266 2440,1310
  other v2: 1060,263.07 1095,263.07 945,288.07 985,288.07 900,333.07 695,505 615,640 445,750 670,810 390,815 580,820 1000,875 810,975 427,985 1000,995 600,1040 980,1080 645,1145 1310,1155 985,1171 440,1250 985,1260 465,1270 735,1285 1380,1315 1110,1325 545,1333
  other v3: 1772.72,779.25 1801.06,779.25 1829.41,779.25 1857.76,779.25 1772.72,807.6 1801.06,807.6 1829.41,807.6 1857.76,807.6 1772.72,835.94 1801.06,835.94 1829.41,835.94 1857.76,835.94 1772.72,864.29 1801.06,864.29 1829.41,864.29 1857.76,864.29
JTAG_TCK: J1.4 U1.14 U3.1 | length 477.3
  Layer 1 - Top Layer w7: J1.4@1651.42,1258.19 1651.42,1195.39 U3.1@1648.66,1192.64 1648.66,1171.34 1660,1160 1755,1160 1765,1150 1765,959.62 1791.38,933.24 U1.14@1791.38,896.8
JTAG_TMS: J1.2 U1.13 U2.1 | length 434.7
  Layer 1 - Top Layer w7: J1.2@1701.42,1258.19 1751.85,1258.19 U2.1@1754.69,1255.35 ; U2.1@1754.69,1255.31 1785,1225 1785,964.62 1807.13,942.5 U1.13@1807.13,896.8
MODE_SELECTION: J3.2 R2.2 U1.9 | length 599.1
  Layer 1 - Top Layer w7: U1.9@1870.12,896.8 1891.43,896.8 1899.62,905 v1(1924.62,905) ; J3.2@1990,1315 2020.01,1345 2063.62,1345 R2.2@2070,1338.62
  Layer 3 - PWR w7: v1(1924.62,905) 1940,905 1990,955 J3.2@1990,1315
NetA1_1: A1.1 C22.1 C24.1 C26.1 C28.1 C30.1 C31.1 C32.1 R9.1 | length 641.4
  Layer 1 - Top Layer w10: v2(755,403.07) A1.1@776.51,372.74
  Layer 4 - Bottom Layer w15: C24.1@1007.9,208.7 1032.44,208.7 1075,166.14 1117.31,208.45 R9.1@1144,208.45
  Layer 4 - Bottom Layer w20: v2(755,403.07) 755,233.07 779.37,208.7 C24.1@1007.9,208.7
NetA1_3: A1.3 R10.1 | length 195.1
  Layer 1 - Top Layer w10: R10.1@602.36,472.44 604.8,470 640,470 685,405 A1.3@728.14,340.8
NetBT1_1: BT1.1 Q1.3
NetC14_1: C14.1 U1.12 | length 91.5
  Layer 1 - Top Layer w7: U1.12@1822.87,896.8 C14.1@1822.87,986.38
  Layer 1 - Top Layer w10: C14.1@1825,986.38 C14.1@1825,988.35
NetC15_1: C15.1 L3.2 L4.1 U1.1 | length 92
  Layer 1 - Top Layer w7: U1.1@1889.8,766.88 1919.12,766.88 L3.2@1929.7,756.3 ; L3.2@1929.32,756.3 L3.2@1929.7,756.3 ; L3.2@1931,756.3 L3.2@1929.7,756.3
  Layer 1 - Top Layer w24: C15.1@1972,756.3 L4.1@2018,756.3
NetC16_1: C16.1 C17.2 L4.2 | length 74.4
  Layer 1 - Top Layer w24: L4.2@2059.65,756.3 C16.1@2100,756.3 C17.2@2134,756.3
NetC17_1: C17.1 R4.1 R5.1 | length 34
  Layer 1 - Top Layer w24: C17.1@2184,756.3 R4.1@2218,756.3
NetC19_2: C19.2 R5.2 R6.1 | length 68
  Layer 1 - Top Layer w24: R5.2@2263,756.3 C19.2@2297,756.3 R6.1@2331,756.3
NetC33_1: C33.1 R11.1 | length 71.8
  Layer 1 - Top Layer w20: R11.1@692.91,775.59 710,758.5 710,725 C33.1@720,715
NetC34_1: C34.1 C36.2 D1.1 D2.2 pad.0@430,862.2 R13.2 U6.1 | length 374
  Layer 1 - Top Layer w15: C36.2@519.68,862.2 C34.1@519.68,641.73 519.68,610.32 526.57,603.43 U6.1@526.57,580.71
  Layer 1 - Top Layer w20: pad.0@430,862.2 C36.2@519.68,862.2
NetC34_2: C34.2 D1.2 D2.1 R11.2 R13.1 U6.4 | length 365
  Layer 1 - Top Layer w15: U6.4@615.16,529.53 585.47,529.53 566.93,548.07 C34.2@566.93,641.73 564.96,643.7 D1.2@564.96,775.59 R11.2@645.67,775.59
NetC36_1: C36.1 R14.1 | length 63.1
  Layer 1 - Top Layer w10: R14.1@547.24,913.39 553.61,913.39 560,907 560,869.13 C36.1@566.93,862.2
NetC38_1: C38.1 pad.0@625.98,1232.28 R17.1 U7.3 | length 225.3
  Layer 1 - Top Layer w10: pad.0@625.98,1232.28 685.04,1173.23 R17.1@716.54,1173.23 C38.1@716.54,1118.11 715.19,1116.76 U7.3@715.19,1063.46
NetC41_1: C41.1 R15.2 R16.1 TP5.1 U7.1 | length 292.8
  Layer 1 - Top Layer w10: R16.1@787.4,1011.81 786.93,1012.28 U7.1@715.19,1012.28 715.19,961.98 716.54,960.63 719.37,960.63 725,955 725,913.43 R15.2@736.85,901.57 791.34,901.57 TP5.1@822.84,870.08
NetC41_2: C41.2 R14.2 R15.1 U7.4 | length 257.8
  Layer 1 - Top Layer w10: R14.2@594.49,913.39 645.04,913.39 R15.1@656.85,901.57 669.29,914.02 669.29,1030.71 636.54,1063.46 U7.4@626.61,1063.46
NetC46_1: C46.1 R18.1 R19.2 U8.3 | length 278
  Layer 1 - Top Layer w10: R18.1@882.52,1086.61 R19.2@882.52,1165.35 938.65,1165.35 952.76,1151.24 C46.1@952.76,1125.98 996.02,1125.98 1018.65,1103.35 U8.3@1041.34,1103.35
NetC47_1: C47.1 R20.1 R21.2 U9.1 | length 279.5
  Layer 1 - Top Layer w10: R21.2@882.52,1322.84 R20.1@882.52,1244.09 905.37,1221.24 952.76,1221.24 C47.1@952.76,1212.6 1006.4,1212.6 1041.34,1177.66 U9.1@1041.34,1168.31
NetC48_2: C48.2 E1.1 R6.2 | length 99.3
  Layer 1 - Top Layer w24: R6.2@2381,756.3 C48.2@2415,756.3 E1.1@2480.32,756.3
NetJ2_2: J2.2 U1.23 | length 890.1
  Layer 1 - Top Layer w7: v1(1694.62,770) 1707.25,782.63 U1.23@1740.2,782.63
  Layer 3 - PWR w7: J2.2@1410,62.99 1530,182.99 1530,495 1585,550 1585,685 1670,770 v1(1694.62,770)
NetJ2_3: J2.3 U1.24 | length 810.2
  Layer 1 - Top Layer w7: v1(1694.62,740) 1721.5,766.88 U1.24@1740.2,766.88
  Layer 3 - PWR w7: J2.3@1510,62.99 1550,102.99 1550,486.72 1605,541.72 1605,650.38 v1(1694.62,740)
NetJ2_4: J2.4 U1.25 | length 792.9
  Layer 1 - Top Layer w7: v1(1724.62,735) 1736.82,747.2 U1.25@1759.88,747.2
  Layer 3 - PWR w7: J2.4@1610,62.99 1570,102.99 1570,478.43 1625,533.43 1625,635.38 v1(1724.62,735)
NetJ2_5: J2.5 U1.26 | length 819
  Layer 1 - Top Layer w7: v1(1753,715) 1767,715 1775.63,723.63 U1.26@1775.63,747.2
  Layer 3 - PWR w7: J2.5@1710,62.99 1590,182.99 1590,470.15 1645,525.15 1645,607 v1(1753,715)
